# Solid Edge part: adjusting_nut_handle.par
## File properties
Title: Adjusting nut handle
Author: Abhinav Rai
Template: Normal.par
Last saved by: Rajat Kamboj
Revision: 19
Application: Solid Edge
Accuracy: 0.99
Material: aluminum
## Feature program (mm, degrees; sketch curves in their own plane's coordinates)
sketch for "unnamed Protrusion 1" plane through (0, 0, 0) normal (0, -1, 0) x-axis (1, 0, 0)
  circle centre (0, 0) radius 9.5123
extrude "unnamed Protrusion 1" add finite 127 symmetric
chamfer "Chamfer_1" setback 1.5748
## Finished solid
Body 1: solid body, 5 faces, 4 edges, 0 vertices.
  Faces by surface: cone 2, plane 2, cylinder 1
  Edges by curve: circle 4
Bounding box of the edges (mm): 19.025 x 127.000 x 19.025, from (-9.5123, -63.5, -9.5123) to (9.5123, 63.5, 9.5123).
Cylindrical faces by radius (mm): R9.5123 x1
Conical faces (half-angle, radius in mm at the cone's reference point): 45 deg R7.9375 x1, 45 deg R9.5123 x1
Planar faces by outward normal: +y 1, -y 1
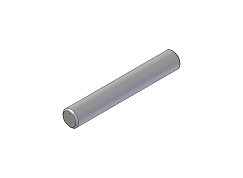
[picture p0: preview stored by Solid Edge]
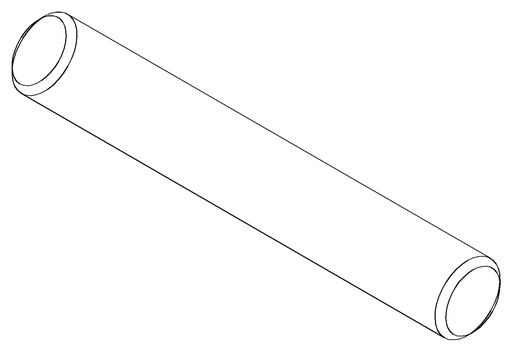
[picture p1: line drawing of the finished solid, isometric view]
